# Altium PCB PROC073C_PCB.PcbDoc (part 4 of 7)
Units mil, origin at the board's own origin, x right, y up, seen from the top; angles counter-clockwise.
Board outline 2165.35 x 2695.12 mil, 8 copper layers (Top Layer, L2_GND, L3_SIGNAL 1, L4_SIGNAL 2, L5_SIGNAL 3, L6_SIGNAL 4, L7_GND, Bottom Layer), stack 55.9 mil thick; 393 components, 319 nets, 1311 pads, 1643 vias.
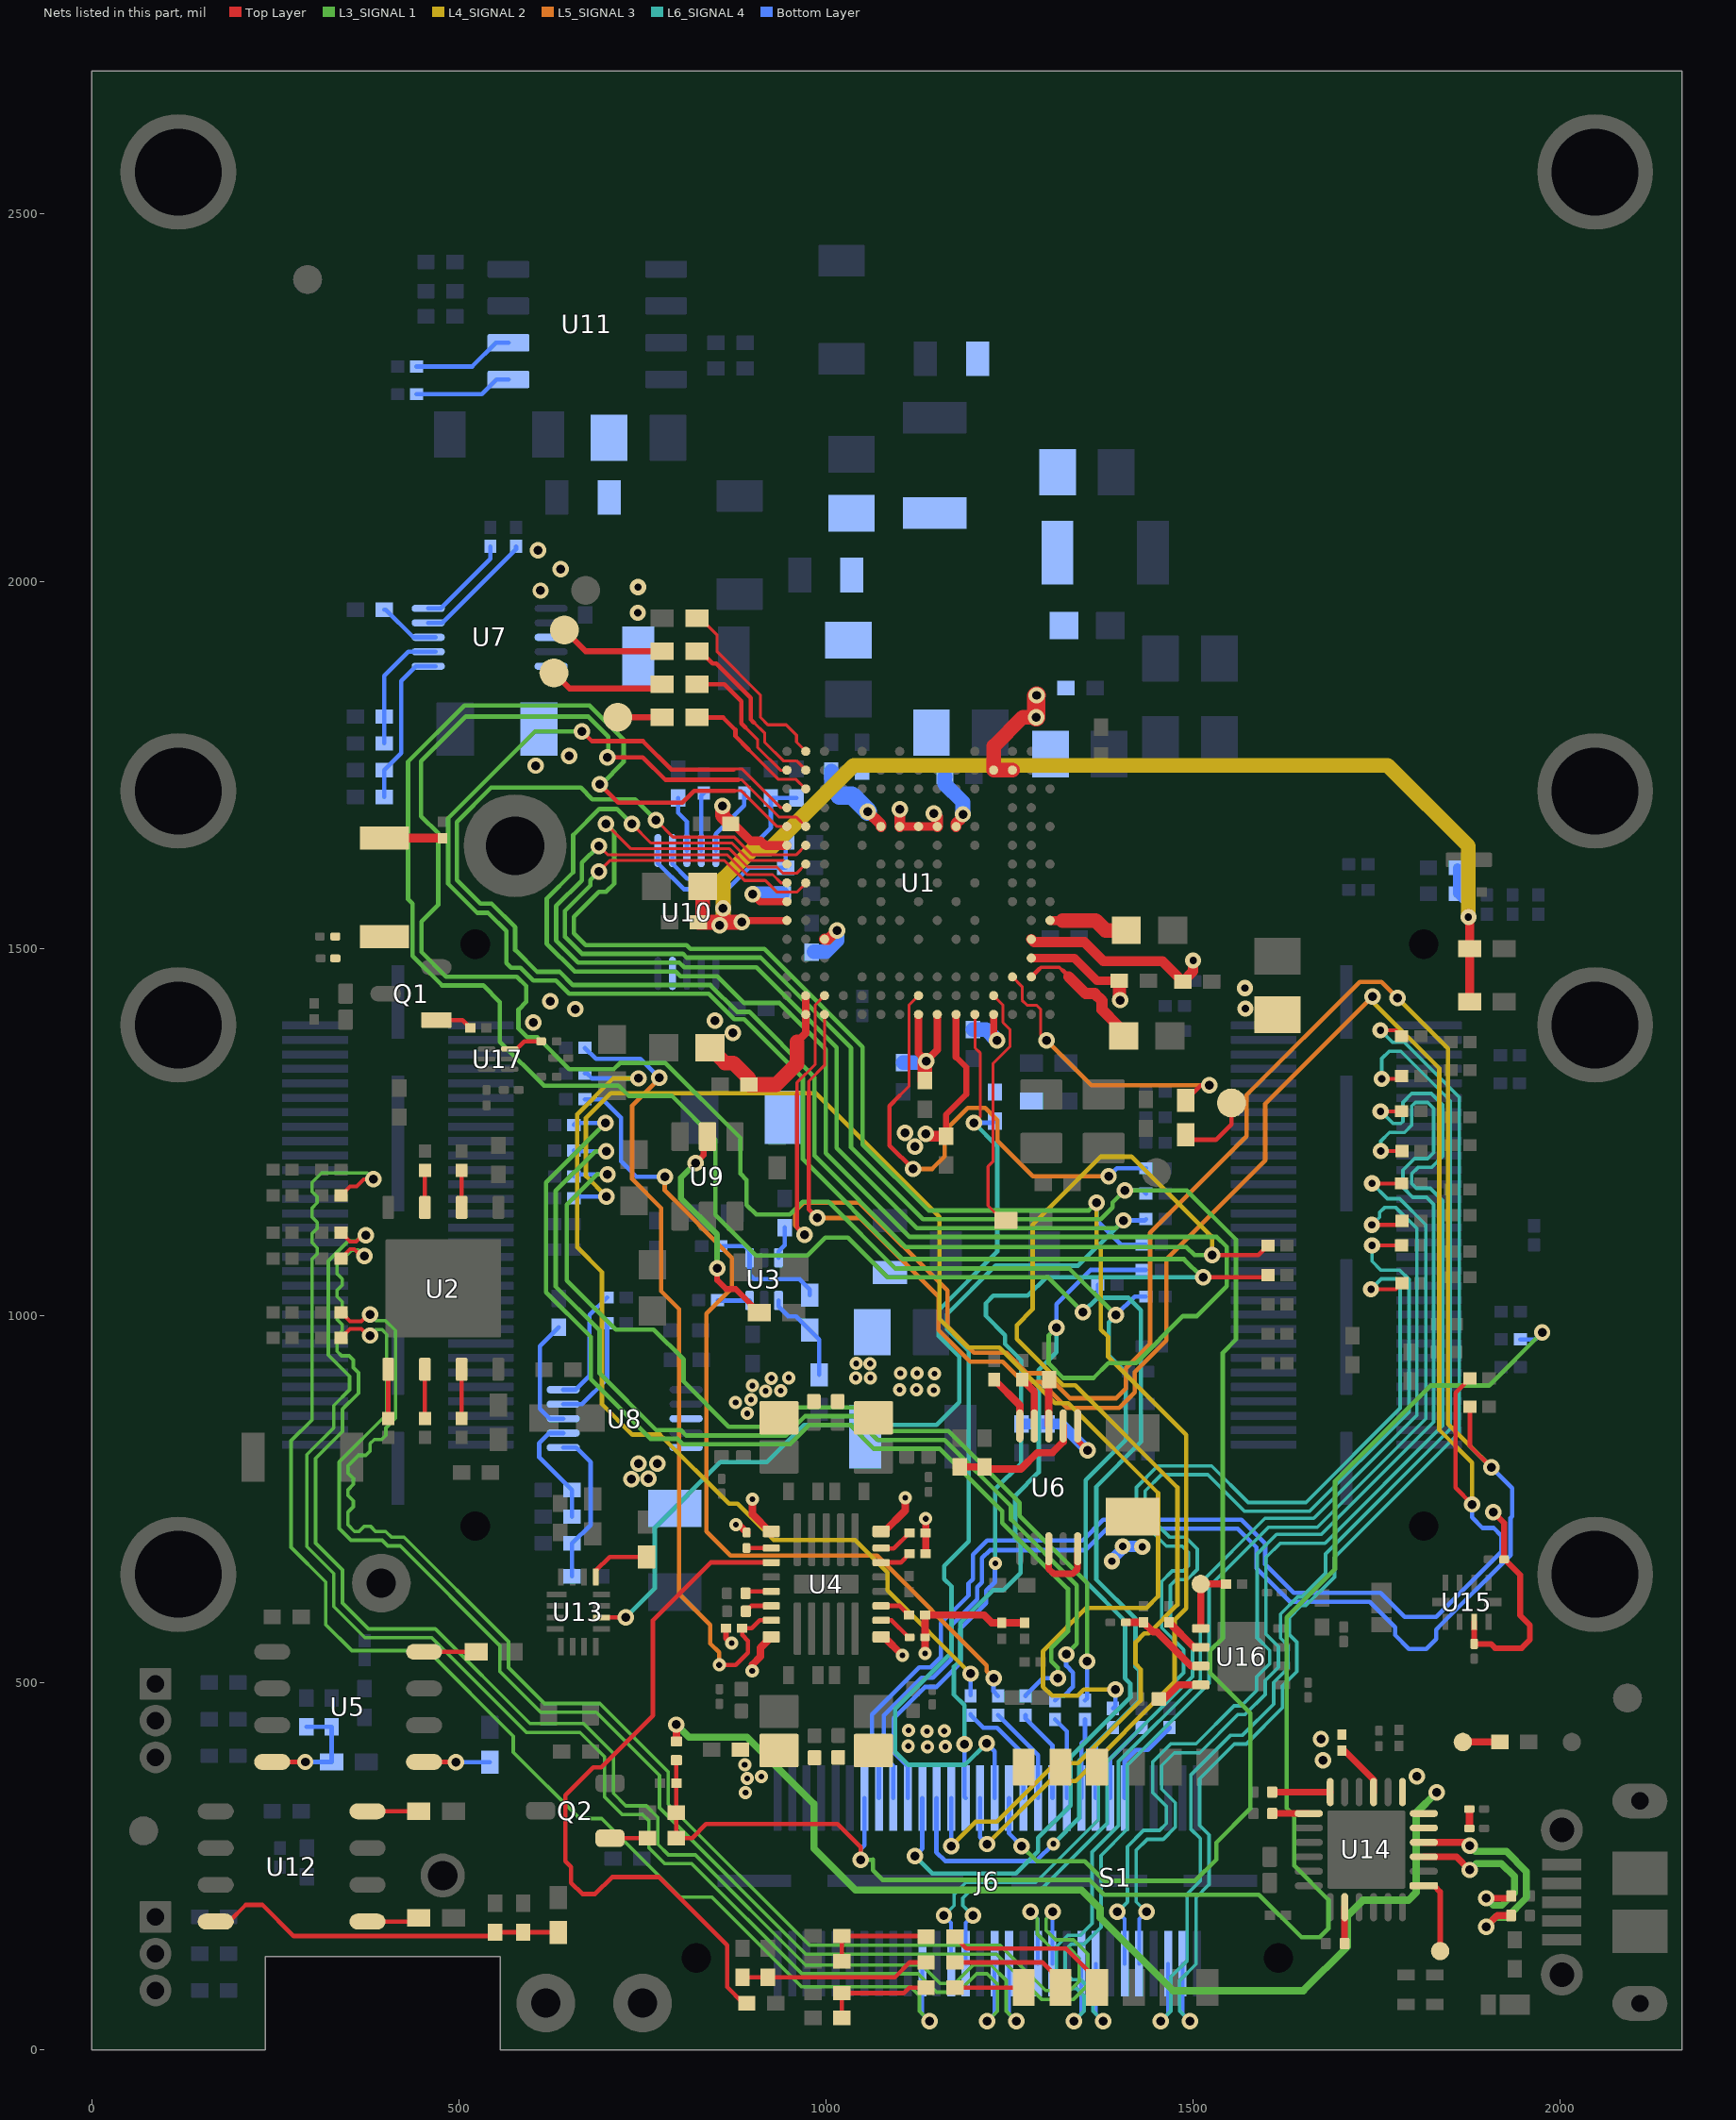
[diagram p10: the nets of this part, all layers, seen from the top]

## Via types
v1: diameter 13.77/15.74 (per signal layer), hole 5.9, Top Layer to L2_GND, tented both sides, 894 vias
v2: diameter 22.4, hole 12.2, Top Layer to Bottom Layer, tented both sides, 510 vias
v3: diameter 18, hole 8, Top Layer to Bottom Layer, tented both sides, 74 vias
v4: diameter 13.78/15.75 (per signal layer), hole 5.9, Top Layer to L2_GND, tented both sides, 72 vias
v5: diameter 22, hole 10, Top Layer to Bottom Layer, tented both sides, 61 vias
v6: diameter 19.68, hole 7.87, Top Layer to Bottom Layer, 16 vias
v7: diameter 13.77/15.74 (per signal layer), hole 5.9, Top Layer to L2_GND, tented top, 14 vias
v8: diameter 20, hole 10, Top Layer to Bottom Layer, tented both sides, 1 vias
v9: diameter 13.78/15.75 (per signal layer), hole 5.9, Top Layer to L2_GND, tented top, 1 vias

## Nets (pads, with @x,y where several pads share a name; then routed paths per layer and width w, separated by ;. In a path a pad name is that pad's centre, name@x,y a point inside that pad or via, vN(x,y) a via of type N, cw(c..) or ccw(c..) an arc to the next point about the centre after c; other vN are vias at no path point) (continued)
NetJ6_22: J6.22 R218.1 | length 1949.4
  Top Layer w5.2: R218.1@339.59,1163.84 351.99,1176.24 360.88,1176.24 370.5,1185.86 v2(383.47,1185.86)
  L3_SIGNAL 1 w4.8: v2(383.47,1185.86) 374.98,1194.35 313.13,1194.35 300.19,1181.41 300.19,1169.03 307.35,1161.87 307.35,1153.8 300.19,1146.63 300.19,1134.25 307.35,1127.09 307.35,1119.02 300.19,1111.85 300.19,1099.47 307.35,1092.31 307.35,1084.24 300.19,1077.07 300.19,858.15 271.76,829.72 271.76,684.49 318.91,637.34 318.91,579.48 354.52,543.87 457.77,543.87 574.27,427.37 574.27,405.68 664.61,315.35 694.6,315.35 801.52,208.43 844.66,208.43 966.67,86.42 1115.14,86.42 1127.31,74.24 1127.31,53.17 v2(1141.05,39.43)
  Bottom Layer w5.2: J6.22@1131.16,117.69 1131.16,49.32 v2(1141.05,39.43)
NetJ6_26: J6.26 R219.1 | length 1630.9
  Top Layer w5.2: v5(1742.18,1036.2) 1775.92,1036.2 R219.1@1784.28,1044.56
  L6_SIGNAL 4 w4.8: v2(1160.63,183.2) 1174.37,196.94 1174.37,212.1 1190.55,228.27 1285.45,228.27 1370.95,313.77 1370.95,397.69 1487.02,513.76 1487.02,545.11 1457.02,575.11 1457.02,637.99 1471.68,652.65 1486.89,652.65 1493.67,659.44 1493.67,677.53 1484.88,686.32 1463.52,686.32 1422.63,727.21 1422.63,766.42 1451.72,795.51 1525.13,795.51 1574.8,745.84 1653.63,745.84 1781.88,874.08 1781.88,1044.62 1776.33,1050.16 1756.14,1050.16 v5(1742.18,1036.2)
  Bottom Layer w5.2: v2(1160.63,183.2) 1170.53,173.3 J6.26@1170.53,117.69
NetJ6_28: J6.28 R220.1 | length 1664.8
  Top Layer w5.2: v5(1743.62,1095.72) R220.1@1783.85,1095.72
  L6_SIGNAL 4 w4.8: v2(1200.11,183.2) 1186.37,196.94 1186.37,207.13 1195.52,216.27 1290.42,216.27 1382.95,308.8 1382.95,392.72 1499.02,508.79 1499.02,550.08 1469.02,580.08 1469.02,633.02 1476.66,640.65 1491.86,640.65 1505.67,654.47 1505.67,682.5 1489.85,698.32 1468.49,698.32 1434.63,732.18 1434.63,761.45 1456.69,783.51 1520.16,783.51 1569.83,733.84 1658.61,733.84 1793.88,869.11 1793.88,1049.59 1781.3,1062.16 1755.57,1062.16 1743.62,1074.11 v5(1743.62,1095.72)
  Bottom Layer w5.2: J6.28@1190.21,117.69 1190.21,173.3 v2(1200.11,183.2)
NetJ6_32: J6.32 R221.1 | length 1959.3
  Top Layer w5.2: R221.1@339.59,1113.02 351.99,1100.62 360.08,1100.62 369.08,1109.62 v2(373.31,1109.62)
  L3_SIGNAL 1 w4.8: v2(373.31,1109.62) 368.47,1109.62 360.27,1101.42 349.22,1101.42 322.31,1074.51 322.31,946.53 351.38,917.46 351.38,899.33 329.71,877.67 329.71,847.36 293.13,810.78 293.13,685.59 329.71,649.01 329.71,604.05 372.12,561.65 463.06,561.65 592.02,432.69 665.03,432.69 698.65,399.07 698.65,344.61 722.44,320.82 750.22,320.82 759.03,312.01 759.03,275.31 780.47,253.86 817.18,253.86 967.15,103.89 1125.58,103.89 1150.66,78.81 1180.28,78.81 1205.36,103.89 1219.51,103.89 1233.42,89.98 1233.42,53.17 v2(1219.69,39.43)
  Bottom Layer w5.2: v2(1219.69,39.43) 1229.58,49.32 J6.32@1229.58,117.69
NetJ6_34: J6.34 R222.1 | length 1959.7
  Top Layer w5.2: R222.1@339.59,1078.02 351.99,1090.42 357.63,1090.42 366.83,1081.22 v2(371.54,1081.22)
  L3_SIGNAL 1 w4.8: v2(371.54,1081.22) 363.34,1089.42 354.19,1089.42 334.31,1069.54 334.31,1057.16 341.47,1049.99 341.47,1041.92 334.31,1034.76 334.31,1026.05 341.47,1018.89 341.47,1010.81 334.31,1003.65 334.31,994.94 341.47,987.78 341.47,979.71 334.31,972.55 334.31,951.5 340.47,945.34 350.59,945.34 356.3,939.63 356.3,929.5 363.38,922.43 363.38,894.36 341.71,872.7 341.71,842.39 305.13,805.81 305.13,690.56 341.71,653.98 341.71,609.02 377.09,573.65 468.03,573.65 596.99,444.69 670,444.69 710.65,404.04 710.65,349.58 727.41,332.82 755.19,332.82 771.03,316.98 771.03,280.28 785.44,265.86 822.15,265.86 972.12,115.89 1130.55,115.89 1155.63,90.81 1175.31,90.81 1200.39,115.89 1224.48,115.89 1245.42,94.95 1245.42,53.17 v2(1259.16,39.43)
  Bottom Layer w5.2: J6.34@1249.27,117.69 1249.27,49.32 v2(1259.16,39.43)
NetJ6_35: J6.35 R148.2 | length 155.1
  Bottom Layer w6: R148.2@1196.94,457.46 R148.2@1196.94,456.22 1214,439.16 1232.89,439.16 1268.95,403.11 J6.35@1268.95,343.28
NetJ6_37: J6.37 R149.2 | length 135.4
  Bottom Layer w6: R149.2@1234.31,456.22 1288.64,401.89 J6.37@1288.64,343.28
NetJ6_38: J6.38 R223.1 | length 1933.7
  Top Layer w5.2: R223.1@339.59,1004.77 351.99,992.37 367.5,992.37 376.59,1001.46 v2(379.02,1001.46)
  L3_SIGNAL 1 w4.8: v2(379.02,1001.46) 387.22,993.26 400.27,993.26 413.84,979.7 413.84,860.42 400.77,847.35 400.77,837.22 395.06,831.51 384.93,831.51 379.22,825.8 379.22,815.67 373.52,809.97 363.39,809.97 349.2,795.78 349.2,785.54 356.37,778.37 356.37,770.3 349.2,763.14 349.2,755.07 356.37,747.91 356.37,739.83 349.2,732.67 349.2,715.18 358.13,706.25 364.31,706.25 371.47,713.41 379.54,713.41 386.7,706.25 400.51,706.25 408.29,698.47 425.38,698.47 567.72,556.13 567.72,520.98 616.52,472.18 692.06,472.18 785.26,378.98 785.26,335 977.48,142.78 1237.24,142.78 1298.95,81.07 1332.07,81.07 1344.69,93.69 1344.69,125.63 1332.05,138.28 1307.45,138.28 1287.86,157.87 1287.86,178.77 1278.74,187.88 v2(1278.74,188.2)
  Bottom Layer w5.2: v2(1278.74,188.2) 1288.64,178.3 J6.38@1288.64,117.69
NetJ6_39: J6.39 R163.2 | length 128.1
  Bottom Layer w6: R163.2@1271.67,456.22 1271.67,452.07 1308.32,415.42 J6.39@1308.32,343.28
NetJ6_40: J6.40 R224.1 | length 1920.9
  Top Layer w5.2: R224.1@339.59,969.77 351.99,982.17 367.48,982.17 376.59,973.06 v2(379.02,973.06)
  L3_SIGNAL 1 w4.8: v2(379.02,973.06) 387.22,981.26 395.3,981.26 401.84,974.73 401.84,865.39 337.2,800.76 337.2,710.21 353.16,694.25 395.54,694.25 403.32,686.47 420.41,686.47 555.72,551.16 555.72,516.01 611.55,460.18 687.09,460.18 773.26,374.01 773.26,330.03 972.51,130.78 1232.27,130.78 1294.2,68.85 1336.82,68.85 1356.69,88.72 1356.69,130.6 1337.02,150.28 1312.42,150.28 1299.86,162.84 1299.86,178.77 1308.97,187.88 v2(1308.97,188.2)
  Bottom Layer w5.2: J6.40@1308.32,117.69 1308.32,188.15 v2@1308.97,188.8
NetJ6_41: J6.41 R164.2 | length 113.6
  Bottom Layer w6: R164.2@1311.95,450.23 1328.01,434.17 J6.41@1328.01,343.28
NetJ6_43: J6.43 R166.2 | length 109
  Bottom Layer w6: J6.43@1347.69,343.28 1347.69,417.53 1352.68,422.52 R166.2@1352.68,450.23
NetJ6_44: J6.44 R225.1 | length 1572
  Top Layer w5.2: v5(1743.35,1123.72) 1778.97,1123.72 R225.1@1784.28,1129.03
  L6_SIGNAL 4 w4.8: v2(1337.8,39.43) 1351.53,53.17 1351.53,73.72 1341.14,84.11 1329.62,84.11 1313.76,99.97 1313.76,140.88 1329.26,156.38 1346.44,156.38 1362.42,172.37 1362.42,269.88 1398.31,305.77 1398.31,392.94 1509.65,504.28 1509.65,635.99 1597.69,724.04 1664.08,724.04 1804.68,864.64 1804.68,1118.81 1776.17,1147.32 1760.45,1147.32 1753.74,1140.61 1753.74,1134.11 v5(1743.35,1123.72)
  Bottom Layer w5.2: v2(1337.8,39.43) 1347.69,49.32 J6.44@1347.69,117.69
NetJ6_45: J6.45 R167.2 | length 105.8
  Bottom Layer w6: J6.45@1367.38,343.28 1367.38,415.98 R167.2@1390.77,439.38
NetJ6_46: J6.46 R226.1 | length 1583.7
  Top Layer w5.2: v5(1743.62,1180.18) R226.1@1783.85,1180.18
  L6_SIGNAL 4 w4.8: v2(1377.27,39.43) 1363.53,53.17 1363.53,78.69 1346.11,96.11 1334.59,96.11 1325.76,104.94 1325.76,135.91 1334.23,144.38 1351.41,144.38 1374.42,167.4 1374.42,264.91 1410.31,300.8 1410.31,387.97 1521.65,499.31 1521.65,631.02 1602.67,712.04 1669.05,712.04 1816.68,859.67 1816.68,1123.78 1781.14,1159.32 1764.49,1159.32 v5(1743.62,1180.18)
  Bottom Layer w5.2: J6.46@1367.38,117.69 1367.38,49.32 v2(1377.27,39.43)
NetJ6_47: J6.47 R168.2 | length 113.9
  Bottom Layer w6: J6.47@1387.06,343.28 1387.06,396.52 R168.2@1429.92,439.38
NetJ6_49: J6.49 R170.2 | length 130.8
  Bottom Layer w6: J6.49@1406.75,343.28 1406.75,393.1 1422.61,408.97 1438.62,408.97 1467.83,438.18 R170.2@1467.83,439.38
NetJ6_50: J6.50 R227.1 | length 1662.4
  Top Layer w5.2: v5(1755.37,1224.38) R227.1@1784.28,1224.38
  L6_SIGNAL 4 w4.8: v2(1396.85,188.2) 1410.46,201.81 1410.46,277.23 1432.38,299.14 1454.19,299.14 1463.62,308.57 1463.62,331.94 1445.01,350.56 1445.01,392.52 1469.51,417.03 1504,417.03 1555.82,468.84 1565.64,468.84 1586.1,489.31 1586.1,508.08 1604.1,526.08 1604.1,544.43 1587.16,561.36 1587.16,675.75 1613.65,702.24 1674.52,702.24 1827.48,855.2 1827.48,1151.71 1817.81,1161.37 1798.93,1161.37 1785.54,1174.76 1785.54,1198.19 1801.27,1213.92 1819.41,1213.92 1827.48,1222 1827.48,1282.33 1819.26,1290.54 1802.62,1290.54 1797.58,1285.5 1797.58,1259.47 1787.83,1249.72 1767.2,1249.72 1755.37,1237.89 v5(1755.37,1224.38)
  Bottom Layer w5.2: v2(1396.85,188.2) 1406.75,178.3 J6.50@1406.75,117.69
NetJ6_52: J6.52 R228.1 | length 1671
  Top Layer w5.2: v5(1755.14,1278.29) 1783.63,1278.29 R228.1@1783.85,1278.52
  L6_SIGNAL 4 w4.8: v2(1436.33,188.2) 1422.46,202.07 1422.46,272.26 1437.35,287.14 1459.16,287.14 1475.62,303.6 1475.62,336.91 1457.01,355.53 1457.01,387.55 1474.48,405.03 1508.97,405.03 1560.79,456.84 1570.61,456.84 1598.1,484.33 1598.1,503.11 1616.1,521.11 1616.1,549.4 1599.16,566.33 1599.16,670.78 1618.62,690.24 1679.49,690.24 1839.48,850.23 1839.48,1156.68 1822.79,1173.37 1803.9,1173.37 1797.54,1179.73 1797.54,1193.22 1806.24,1201.92 1824.38,1201.92 1839.48,1217.03 1839.48,1287.3 1824.23,1302.54 1797.65,1302.54 1785.58,1290.47 1785.58,1264.44 1782.86,1261.72 1772.17,1261.72 1755.6,1278.29 v5(1755.14,1278.29)
  Bottom Layer w5.2: J6.52@1426.43,117.69 1426.43,178.3 v2(1436.33,188.2)
NetJ6_56: J6.56 R229.1 | length 1712.9
  Top Layer w5.2: v5(1756.84,1322.52) 1780.15,1322.52 R229.1@1783.85,1326.22
  L6_SIGNAL 4 w4.8: v2(1455.91,39.43) 1469.64,53.17 1469.64,99.86 1491.92,122.14 1491.92,212.81 1509.62,230.51 1509.62,288.19 1496.76,301.05 1496.76,374.52 1551.09,428.86 1567.34,428.86 1609.55,471.07 1609.55,500.7 1629.22,520.37 1629.22,550.58 1618.87,560.93 1618.87,593.88 1642.25,617.26 1648.32,617.26 1680.35,649.3 1680.35,675.83 1850.28,845.75 1850.28,1292.56 1782.66,1360.18 1766.99,1360.18 1756.84,1350.03 v5(1756.84,1322.52)
  Bottom Layer w5.2: v2(1455.91,39.43) 1465.8,49.32 J6.56@1465.8,117.69
NetJ6_58: J6.58 R230.1 | length 1713.2
  Top Layer w5.2: v5(1755,1388.58) 1775.98,1388.58 R230.1@1783.85,1380.71
  L6_SIGNAL 4 w4.8: v2(1495.38,39.43) 1481.64,53.17 1481.64,94.89 1503.92,117.17 1503.92,207.84 1520.68,224.59 1521.62,225.54 1521.62,293.16 1508.76,306.02 1508.76,369.55 1556.06,416.86 1572.31,416.86 1621.55,466.1 1621.55,495.73 1641.22,515.4 1641.22,555.55 1630.87,565.9 1630.87,588.91 1647.22,605.26 1653.29,605.26 1692.35,644.33 1692.35,670.85 1862.28,840.78 1862.28,1297.53 1787.63,1372.18 1771.39,1372.18 v5(1755,1388.58)
  Bottom Layer w5.2: J6.58@1485.49,117.69 1485.49,49.32 v2(1495.38,39.43)
NetQ1_1: Q1.1 R171.2 | length 50.6
  Top Layer w6: Q1.1@469.47,1402.58 505.1,1402.58 R171.2@515.68,1391.99
NetQ2_1: Q2.1 R179.2 | length 51.6
  Top Layer w6: Q2.1@705.91,288.6 R179.2@757.47,288.6
NetR2_1: R2.1 R101.2 U6.2 | length 179.2
  Top Layer w10: R101.2@1182.13,794.19 R2.1@1215.81,794.22 1218.77,791.26 1265.4,791.26 1287.55,813.41 1308.25,813.41 1323.04,828.2 U6.2@1323.04,849.93
NetR3_1: R3.1 R70.2 R71.1 U5.8 | length 163.1
  Top Layer w6: U5.8@245.94,392.41 v2(290.94,392.41)
  Bottom Layer w6: v2(290.94,392.41) R3.1@326.89,392.41 R70.2@326.89,440.22 R71.1@292.59,440.22
NetR14_1: R14.1 R103.2 U6.1 | length 143.9
  Top Layer w8: U6.1@1342.73,849.93 1342.73,830.32 v2(1356.41,816.64)
  Bottom Layer w15: R103.2@1266.47,852.83 1320.22,852.83 v2(1356.41,816.64)
NetR25_1: R25.1 U6.5 | length 77.6
  Top Layer w10: R25.1@1229.01,913.08 1263.99,878.1 U6.5@1263.99,849.93
NetR29_1: R29.1 U6.4 | length 70
  Top Layer w10: R29.1@1267.18,913.08 1283.67,896.58 U6.4@1283.67,849.93
NetR45_1: R45.1 U2.5 | length 66.8
  Top Layer w6: R45.1@403.88,860.18 U2.5@403.88,926.95
NetR46_2: R46.2 U2.2 | length 50.7
  Top Layer w6: U2.2@503.88,1147.43 R46.2@503.88,1198.11
NetR47_2: R47.2 U2.3 | length 50.7
  Top Layer w6: U2.3@453.88,1147.43 R47.2@453.88,1198.11
NetR48_1: R48.1 U2.6 | length 66.8
  Top Layer w6: R48.1@453.88,860.18 U2.6@453.88,926.95
NetR51_1: R51.1 U2.7 | length 66.8
  Top Layer w6: R51.1@503.88,860.18 U2.7@503.88,926.95
NetR54_1: R54.1 U3.3 | length 44.6
  Bottom Layer w6: U3.3@935.43,1078.9 935.43,1087.51 943.74,1095.83 R54.1@943.74,1120.09
NetR55_2: R55.2 U3.6 | length 43.8
  Bottom Layer w6: R55.2@852.47,1021.13 852.97,1020.64 U3.6@896.06,1020.64
NetR56_2: R56.2 R151.1 U3.1 | length 172.4
  Bottom Layer w6: R56.2@856.74,1094.77 889.16,1094.77 896.06,1087.87 896.06,1055.71 902,1049.77 964,1049.77 977.93,1035.84 R151.1@977.93,1027.84
NetR57_1: R57.1 R151.2 U3.4 | length 130.1
  Bottom Layer w6: U3.4@935.43,1020.64 935.43,1012.53 948.74,999.22 959.31,999.22 R151.2@977.93,980.6 990.93,967.6 R57.1@990.93,919.72
NetR72_2: R72.2 U1.P1 | length 260.2
  Top Layer w4.02: R72.2@824.21,1949.77 828.74,1949.77 851.87,1926.64 851.87,1904.07 910.74,1845.2 910.74,1814.77 920.91,1804.6 945.93,1804.6 959.85,1790.67 959.85,1781.1 U1.P1@972.43,1768.52 U1.P1@972.64,1768.31
NetR73_2: R73.2 U1.P2 | length 239.8
  Top Layer w4: 901.74,1807.95 916.74,1792.95 916.74,1780.57 941.73,1755.58 959.78,1755.58 U1.P2@972.64,1742.72
  Top Layer w6: R73.2@824.21,1904.77 828.74,1904.77 845.37,1888.14 850.59,1888.14 897.74,1840.99 897.74,1811.95 901.74,1807.95
NetR74_2: R74.2 U1.P3 | length 193.7
  Top Layer w4: 895.24,1770.48 935.43,1730.29 959.48,1730.29 U1.P3@972.43,1717.34
  Top Layer w6: R74.2@824.21,1814.77 824.41,1814.57 859.94,1814.57 876.74,1797.77 876.74,1788.97 895.24,1770.48
NetR75_2: R75.2 U1.R2 | length 195
  Top Layer w4.02: 890.74,1800.74 906.73,1784.75 906.73,1774.11 938.12,1742.72 U1.R2@947.05,1742.72
  Top Layer w6: R75.2@824.21,1859.77 861.57,1859.77 884.74,1836.6 884.74,1806.74 890.74,1800.74
NetR76_2: R76.2 U1.C13 | length 400.4
  Top Layer w4: U1.C13@1254.13,1461.22 1267.08,1448.28 1267.08,1429.63 1274.08,1422.63 1287.08,1422.63 1292.08,1417.63 1292.08,1383.28 v2(1300.59,1374.77)
  Top Layer w6: R76.2@1490,1293.39 1510.38,1313.77 v2(1522,1313.77)
  L5_SIGNAL 3 w6: v2(1300.59,1374.77) 1361.59,1313.77 v2(1522,1313.77)
NetR77_2: R77.2 U1.D14 | length 340
  Top Layer w4: U1.D14@1228.54,1435.63 1241,1423.18 1241,1399.36 1250.59,1389.77 1250.59,1366.31 1227.29,1343.01 1227.29,1209.82 1220.74,1203.27 1220.74,1149.77 1240.74,1129.77 R77.2@1245.12,1129.77
NetR78_2: R78.2 U5.1 | length 91.4
  Top Layer w6: U5.1@452.64,392.41 v2@497.63,392.41
  Bottom Layer w6: v2(495.99,392.09) R78.2@542.39,392.09
NetR80_2: R80.2 U5.4 | length 71.2
  Top Layer w6: U5.4@452.64,542.41 R80.2@523.88,542.41
NetR83_2: R83.2 R84.1 R216.1 U12.8 | length 495.6
  Top Layer w6: U12.8@169.09,175.13 187.33,175.13 209.99,197.79 232.95,197.79 275.44,155.3 544.39,155.3 R83.2@549.57,160.48 R84.1@587.71,160.48 R216.1@635.54,160.48
NetR85_2: R85.2 U12.1 | length 71.7
  Top Layer w6: U12.1@375.78,175.13 440.44,175.13 R85.2@445.44,180.13
NetR87_2: R87.2 U12.4 | length 69.7
  Top Layer w6: U12.4@375.78,325.13 R87.2@445.44,325.13
NetR89_2: R89.2 U13.13 | length 85.3
  Top Layer w6: U13.13@686.41,644.19 686.41,652.64 705.38,671.61 R89.2@755.42,671.61
NetR91_1: R91.1 U14.3 | length 248.9
  Top Layer w9.42: U14.3@1814.14,263.2 1858.43,263.2 v2(1876.29,245.34) ; v2(1898.86,206.79) 1929.73,206.79 R91.1@1932.91,209.97
  L3_SIGNAL 1 w9.42: v2(1876.29,245.34) 1885.13,254.18 1919.66,254.18 1937.37,236.47 1937.37,214.13 1920.32,197.08 1908.57,197.08 v2(1898.86,206.79)
NetR92_1: R92.1 U14.4 | length 303.5
  Top Layer w9.42: U14.4@1814.14,282.88 1871.86,282.88 v2(1876.29,278.45) ; v2(1898.86,168.11) 1914.06,183.31 R92.1@1932.91,183.31
  L3_SIGNAL 1 w9.42: v2(1876.29,278.45) 1884.13,270.61 1926.46,270.61 1953.79,243.27 1953.79,207.33 1927.12,180.66 1911.41,180.66 v2(1898.86,168.11)
NetR93_2: R93.2 U14.9 | length 76.2
  Top Layer w9: R93.2@1702.37,407.66 1705.75,407.66 1745.65,367.76 U14.9@1745.65,351.37
NetR94_2: R94.2 U6.3 | length 63.4
  Top Layer w10: U6.3@1303.36,849.93 1303.36,912.57 R94.2@1303.87,913.08
NetR96_1: R96.1 U14.20 | length 49.5
  Top Layer w9: R96.1@1706.28,145.26 U14.20@1706.28,194.71
NetR97_1: R97.1 U14.12 | length 79
  Top Layer w9: R97.1@1607.62,351.37 U14.12@1686.6,351.37
NetR98_2: R98.2 U14.13 | length 49.9
  Top Layer w9: R98.2@1607.62,322.25 U14.13@1657.48,322.25
NetR102_2: R102.2 R120.2 U16.3 | length 126.7
  Top Layer w10: R102.2@1408.25,582.46 R120.2@1432.23,582.48 ; R120.2@1432.23,582.48 1445.38,569.33 1450.87,569.33 1497.11,523.08 U16.3@1510.32,523.08
NetR104_1: R104.1 R113.2 U7.2 | length 175.5
  Bottom Layer w6: R104.1@398.53,1779.32 R113.2@398.53,1815.75 398.53,1871.44 431.15,1904.06 U7.2@458.41,1904.06 U7.2@468.41,1904.06
NetR105_1: R105.1 R114.2 U7.1 | length 222.5
  Bottom Layer w6: R114.2@398.53,1706.46 R105.1@398.53,1742.89 421.59,1765.95 421.59,1864.34 441.62,1884.37 U7.1@458.41,1884.37 U7.1@468.41,1884.37
NetR106_1: R106.1 R116.2 U8.2 | length 157.1
  Bottom Layer w6: U8.2@642.2,840.21 623.2,840.21 609.47,826.48 609.47,807.42 R116.2@654.32,762.57 R106.1@654.32,726.36
NetR107_1: R107.1 R117.2 U8.1 | length 211.5
  Bottom Layer w6: U8.1@642.2,820.53 659.67,820.53 679.64,800.56 679.64,715.46 R117.2@654.32,690.14 R107.1@654.32,645.31
NetR108_1: R108.1 U7.5 | length 129.5
  Bottom Layer w6: U7.5@458.41,1963.11 475.48,1963.11 542.98,2030.62 R108.1@542.98,2047.59
NetR109_1: R109.1 U8.5 | length 160.4
  Bottom Layer w6: U8.5@642.2,899.27 659.4,899.27 678.11,917.98 678.11,1000.87 R109.1@702.01,1024.77
NetR110_1: R110.1 U7.4 | length 165
  Bottom Layer w6: U7.4@458.41,1943.43 477.67,1943.43 577.98,2043.74 R110.1@577.98,2047.59
NetR111_1: R111.1 U8.4 | length 149.9
  Bottom Layer w6: U8.4@642.2,879.59 667.74,879.59 702.01,913.85 R111.1@702.01,989.77
NetR112_2: R112.2 U7.3 | length 85.5
  Bottom Layer w6: R112.2@398.53,1961.46 400.43,1961.46 438.16,1923.74 U7.3@458.41,1923.74 U7.3@468.41,1923.74
NetR115_2: R115.2 U8.3 | length 159.1
  Bottom Layer w6: R115.2@636.16,984.35 610.41,958.6 610.41,873.29 623.8,859.9 U8.3@642.2,859.9
NetR118_2: R118.2 TP8.1 U16.1 | length 94.9
  Top Layer w10: U16.1@1510.32,574.26 TP8.1@1510.32,634.76 R118.2@1544.77,634.76
NetR119_1: R119.1 U16.2 | length 57.3
  Top Layer w10: R119.1@1467.08,582.48 1500.89,548.67 U16.2@1510.32,548.67
NetR121_2: R121.2 U16.4 | length 65
  Top Layer w10: R121.2@1453.31,478.28 1460.9,478.28 1480.1,497.49 U16.4@1510.32,497.49
NetR138_2: R138.2 U17.3 | length 47.2
  Top Layer w6: U17.3@569.32,1363.26 578.93,1363.26 589.3,1373.63 R138.2@612.21,1373.63
NetR139_1: R139.1 R146.2 U10.2 | length 264.5
  Bottom Layer w6: U10.2@790.91,1633.43 790.9,1615.45 811.08,1595.27 855.5,1595.27 925,1664.77 R146.2@925,1705.08 R139.1@960,1705.09
NetR142_1: R142.1 R147.2 U10.1 | length 253.1
  Bottom Layer w6: U10.1@771.22,1633.43 771.22,1616.06 806.51,1580.77 866,1580.77 895,1609.77 R147.2@945.31,1609.77 R142.1@945.32,1644.77
NetR143_1: R143.1 U10.5 | length 94.4
  Bottom Layer w6: U10.5@849.96,1633.43 849.96,1655.99 888.74,1694.77 R143.1@888.74,1711.78
NetR144_1: R144.1 U10.4 | length 79.8
  Bottom Layer w6: U10.4@830.28,1633.43 830.27,1708.31 R144.1@833.74,1711.78
NetR145_2: R145.2 U10.3 | length 76.6
  Bottom Layer w6: R145.2@798.74,1705.09 798.74,1684.77 810.59,1672.92 U10.3@810.59,1633.43
NetR159_1: R159.1 U11.6 | length 138.5
  Bottom Layer w6: R159.1@442.58,2292.44 518.2,2292.44 550.53,2324.77 U11.6@567.72,2324.77
NetR160_1: R160.1 U11.5 | length 133.4
  Bottom Layer w6: R160.1@442.58,2254.9 531.38,2254.9 551.25,2274.77 U11.5@567.72,2274.77
NetR196_2: R196.2 U9.5 | length 306.3
  Top Layer w8: v2(822.43,1207.86) 833.46,1218.88 833.46,1238.62 U9.5@838.74,1243.9 ; v2(851.75,1064.74) 851.75,1048.52 864.05,1036.22 877.13,1036.22 R196.2@908.98,1004.37
  L3_SIGNAL 1 w8: v2(822.43,1207.86) 802.54,1187.97 802.54,1159.73 851.75,1110.52 v2(851.75,1064.74)
NetR203_2: R203.2 R204.1 R205.2 | length 151.4
  Top Layer w6: R205.2@1021.73,43.89 R203.2@1021.73,77.62 1105.92,77.62 1113.46,85.15 R204.1@1136.29,85.15
NetR204_2: R204.2 S1.1 | length 93.5
  Top Layer w6: R204.2@1175.66,85.15 S1.1@1269.21,85.15
NetR206_2: R206.2 R207.1 R208.2 | length 258.4
  Top Layer w6: R208.2@886.26,99.3 R206.2@920.56,99.3 1093.84,99.3 1114.01,119.47 R207.1@1136.29,119.47
NetR207_2: R207.2 S1.2 | length 163.3
  Top Layer w6: R207.2@1175.66,119.47 1294.32,119.47 1319.21,94.58 S1.2@1319.21,85.15
NetR209_2: R209.2 R210.1 R211.2 | length 148.5
  Top Layer w6: R211.2@1021.73,120.94 R209.2@1021.73,154.42 ; R209.2@1021.73,155.42 1135.29,155.42 R210.1@1136.29,154.42
NetR210_2: R210.2 S1.3 | length 228.4
  Top Layer w6: R210.2@1175.66,153.78 1191.03,138.41 1326.9,138.41 1369.21,96.1 S1.3@1369.21,85.15
NetR213_1: R213.1 S3.2 | length 79.3
  Top Layer w12: S3.2@398.63,1650.24 R213.1@477.94,1650.24
NetR214_1: R214.1 R215.2 S3.1
NetTP1_1: TP1.1 U14.1 | length 106.3
  Top Layer w8: U14.1@1814.14,223.83 1828.09,223.83 1836.32,215.59 TP1.1@1836.32,134.9
PGOOD: J6.13 R13.2 R179.1 R182.2 R198.1 R201.2 | length 2236.1
  Top Layer w6: R198.1@796.29,394.85 R182.2@796.29,323.18 R179.1@796.29,288.6 817.72,288.6 836.85,307.73 1015.97,307.73 1047.36,276.34 v2(1047.36,259.1)
  L3_SIGNAL 1 w6: v2(1047.36,259.1) 1062.93,259.1 1063.77,259.93 1063.77,245.1 1076.99,231.88 1358.51,231.88 1378.73,211.66 1589.53,211.66 1647.56,153.63 1672.49,153.63 1684.07,165.21 1684.07,204.83 1637.71,251.19 1637.71,319.2 1627.46,329.45 1627.46,589.41 1693.21,655.17 1693.21,775.09 1823.07,904.95 1903.04,904.95 v2(1975.14,977.05)
  Bottom Layer w6: v2(1047.36,259.1) 1047.36,274.13 1052.42,279.19 J6.13@1052.42,343.28 ; R13.2@1945.35,967.82 1965.91,967.82 v2(1975.14,977.05)
PMIC_1V0: C66.1 L6.1 R199.1 U4.1 U7.8 U7.10 | length 55.9
  Top Layer w10: v3(899.89,750.35) 899.89,729.75 923.31,706.33 U4.1@925.53,706.33
  other v2: 601.54,1399.37 658.78,1417.56 624.34,1428.01 604.7,1749.01 650.42,1762.42
  other v3: 892.86,866.84 877.02,881.89 898.08,885.59 917.87,897.49 938.49,897.98 899.69,904.74 925.74,914.81 949.46,915.49
PMIC_1V2: C62.1 L5.1 R193.1 U4.14 U8.8 U8.10 | length 39.1
  Top Layer w5.5: U4.14@1075.13,562.63 U4.14@1079.07,562.63
  Top Layer w10: U4.14@1079.07,562.63 v3(1103.95,537.75)
  other v2: 735.09,777.47 758.48,778.37 744.73,798.74 770.32,798.49
  other v3: 1138.38,413.11 1112.03,413.92 1162.47,413.32 1137.61,434.3 1161.07,434.5 1112.33,435.37
PMIC_1V8: C67.1 L8.1 R192.1 U4.21 U6.8 U6.10 | length 214.4
  Top Layer w9: U6.8@1303.36,682.61 1303.36,655.27 1310.07,648.56 1335.8,648.56 1342.73,655.49 U6.10@1342.73,682.61
  Top Layer w10: U4.21@1075.13,706.33 1079.59,706.33 1107.94,734.68 v3(1107.94,752)
  Bottom Layer w15: v5(1389.19,665.71) 1389.19,667.77 1404.24,682.81 v5(1404.24,686.06) v5@1430.74,686.06
  other v3: 1146.72,898.68 1100.26,899.36 1123.08,899.41 1147.84,921.1 1101.37,921.78 1124.2,921.83
  other v5: 1430.74,685.34
PMIC_3V3: C61.1 L4.1 L12.2 U4.8 | length 57.1
  Top Layer w10: v3(899.54,516.33) 899.54,524.61 910.76,535.83 910.76,547.87 U4.8@925.53,562.63
  other v3: 890.52,350.82 892.73,370.09 912.21,372.62 889.27,388.65
PMIC_CLK: R202.2 U4.3 | length 969.3
  Top Layer w6: R202.2@892.19,64.04 887.49,64.04 865.54,85.99 865.54,142.78 772.71,235.61 708.71,235.61 685.72,212.62 668.23,212.62 653.07,227.78 653.07,249.47 645.25,257.29 645.25,347.13 683.28,385.15 693.72,385.15 764.37,455.8 764.37,585.5 842.88,664.01 U4.3@925.53,664.01
PMIC_EN1: R140.1 R188.1 U4.7 | length 1108.6
  Top Layer w6: v3(854.61,524.55) 877.19,524.55 893.81,541.17 893.81,557.43 885.96,565.28 R188.1@885.96,574.5 898.93,574.5 909.7,585.27 U4.7@925.53,585.27
  L5_SIGNAL 3 w6: v2(773.04,1323.93) 773.04,1322.99 736.17,1286.12 736.17,1186.03 775.68,1146.52 775.68,1033.43 800.07,1009.04 800.07,621.61 842.54,579.14 842.54,553.66 854.61,541.59 v3(854.61,524.55)
  Bottom Layer w6: R140.1@671.74,1364.77 686.71,1349.79 747.18,1349.79 v2(773.04,1323.93)
PMIC_EN2: R189.1 U4.15 | length 48.4
  Top Layer w6: U4.15@1075.13,585.27 1089.29,585.27 1112.56,562 R189.1@1113.9,562
PMIC_EN3: R190.1 U4.2 | length 33.6
  Top Layer w6: R190.1@891.97,683.69 U4.2@925.53,683.69
PMIC_NINT: R177.1 U4.19 | length 43.6
  Top Layer w6: U4.19@1075.13,664.01 1101.78,664.01 R177.1@1113.78,676.01
PMIC_NRST: R187.1 U4.20 | length 47.8
  Top Layer w6: U4.20@1075.13,683.69 1075.82,683 1092.43,683 R187.1@1113.78,704.35
PMIC_PGOOD: R176.1 U4.16 | length 43
  Top Layer w6: U4.16@1075.13,604.95 1100.49,604.95 R176.1@1112.94,592.5
PMIC_SCL: R181.2 U4.5 | length 36
  Top Layer w6: R181.2@890.6,622 893.24,624.64 U4.5@925.53,624.64
PMIC_SDA: R180.2 U4.6 | length 37.7
  Top Layer w6: R180.2@890.94,597.5 898.39,604.95 U4.6@925.53,604.95
PMICOUT_3V3: C44.2 C45.2 C48.1 L11.1 R93.1 R100.2 R198.2 S1.10 S1.11 S1.12 TP10.1 U14.5 U14.6 U14.7 U15.8 | length 1835.2
  Top Layer w7.87: U15.8@1882.6,583.41 C48.1@1882.6,553.12 1905.58,553.12 1911.29,547.41 1947.13,547.41 1958.57,558.85 1958.57,578.57 1945.19,591.95 1945.19,647.14 1924.16,668.16 R100.2@1923.32,668.16 1923.42,668.26 1923.42,717.68 v2(1908.49,732.61)
  Top Layer w10: R198.2@796.29,420.44 v2(796.29,443.16) ; TP10.1@1867.15,419.58 L11.1@1917.5,419.58 ; C44.2@1876.11,301.92 C45.2@1876.11,328.23
  L3_SIGNAL 1 w10: v2(796.29,443.16) 813.35,426.1 892.57,426.1 983.59,335.07 983.59,274.71 1040.43,217.88 1348,217.88 1373.08,192.8 1373.08,180.58 1472.64,81.01 1649.95,81.01 1710.06,141.12 1710.06,183.09 1731.04,204.07 1792.99,204.07 1803.66,214.74 1803.66,323.07 v2(1831.39,350.8)
  other v2: 1804.41,372.66 1676.57,394.51 1673.89,423.82 611.41,1987.35 638.98,2016.51 607.69,2042.36
PMICVIO_3V3: R176.2 R177.2 R186.1 R187.2 R188.2 R189.2 R190.2 R194.2 | length 281.7
  Top Layer w8: R188.2@863.91,574.5 863.91,560.87 v3@870.6,554.18
  Top Layer w10: v3(877.5,715.36) 881.34,715.36 R190.2@891.97,704.73 ; v3(1134.94,540) R189.2@1134.94,562 1134.99,562.05 R176.2@1134.99,592.5 1215.16,592.5 1225.69,581.97 R194.2@1239.41,581.97 R186.1@1270.29,581.97 ; R177.2@1135.83,676.01 R187.2@1135.83,704.35 v3(1135.83,723.6)
  other v3: 871.6,554.18
RADAR_1P0_RF1: C19.2 C23.2 C78.1 C79.1 L3.2 U1.G5 U1.H5 U1.J5 | length 94.3
  Top Layer w12: U1.J5@1100.39,1666.16 U1.G5@1151.57,1666.16
  Top Layer w15: U1.J5@1100.39,1666.16 v2(1100.38,1689.67) ; v2(1146.87,1683.84) 1151.56,1679.15 U1.G5@1151.57,1666.16
RADAR_1P0_RF2: C20.2 C24.2 C76.1 C77.1 L2.2 R1.1 U1.C2 U1.D2 | length 162.3
  Top Layer w20: U1.C2@1254.13,1742.72 1228.54,1742.72 1228.54,1775.5 1268.02,1814.98 v2(1285.98,1814.98)
  Top Layer w25: v2(1285.98,1814.98) 1285.98,1843.73 v2(1286.98,1844.73)
RADAR_1V2: C25.2 C26.2 C27.2 C28.2 C29.2 C30.1 C80.1 C81.1 L7.2 U1.G15 U1.H15 U1.N11 U1.P14 U1.P15 U1.R6 | length 634.2
  Top Layer w10: 960.59,1372.92 972.43,1384.77 U1.P14@972.43,1435.84 ; U1.H15@1125.98,1410.25 1125.97,1357.39 1135.59,1347.77 v2(1136.52,1346.84) 1151.56,1361.88 U1.G15@1151.57,1410.25
  Top Layer w12: C28.2@870.28,1669.77 874.13,1669.77 897.27,1646.63 911.08,1646.63 917.08,1640.63 918.08,1640.63 ; 918.35,1640.36 U1.R6@947.05,1640.36
  Top Layer w15: U1.N11@998.03,1512.61 1003.1,1512.62 v2(1015.27,1524.79)
  Top Layer w20: C27.2@842.09,1364.77 862.55,1344.3 873.86,1344.3 895.28,1322.88 C25.2@895.28,1314.77 932.39,1314.77 960.59,1342.97 960.59,1372.92 ; v2(858.92,1694.27) 858.92,1681.12 C28.2@870.28,1669.77 ; C26.2@1134.5,1320.46 1134.5,1346.68 v2@1135.59,1347.77
  Bottom Layer w20: C29.2@983.87,1495.54 999.57,1495.54 1015.27,1511.24 v2(1015.27,1524.79) ; C30.1@1105,1344.45 v2@1129.04,1344.45
  other v2: 872.95,1385.12 848.87,1401.61
  other v5: 743.79,1957.02 744.02,1992.11
RADAR_1V4_APLL: C22.2 U1.A10 | length 109.3
  Top Layer w12: U1.A10@1305.31,1538 1322.36,1538
  Top Layer w20: 1322.36,1538 1367.36,1538 1380.59,1524.77 C22.2@1409.1,1524.77
RADAR_1V4_SYNTH: C18.2 U1.B13 | length 201.1
  Top Layer w4.5: 1290.62,1472.53 1292.6,1474.52 1317.84,1474.52 1322.59,1469.77
  Top Layer w6: U1.B13@1279.52,1461.43 1290.62,1472.53 ; 1322.59,1469.77 1330.7,1461.65
  Top Layer w15: 1330.7,1461.65 1353.7,1438.66 1366.11,1438.66 1375.89,1428.88 1375.89,1416.47 1397.03,1395.33 C18.2@1397.03,1393.48 ; C18.2@1397.03,1393.48 1397.03,1381.18 C18.2@1405.28,1381.18 1405.28,1385.22 C18.2@1397.03,1393.48
RADAR_1V8: C5.2 C9.2 C10.2 C11.2 C12.2 C13.2 C14.2 C15.2 C82.1 C83.1 L1.2 U1.B11 U1.B12 U1.D15 U1.F5 U1.K5 U1.R9 | length 787.6
  Top Layer w10: v2(900.17,1573.84) 910.21,1563.8 U1.R9@946.84,1563.8 ; U1.D15@1228.54,1410.04 1228.54,1379.17 v2(1232.87,1374.84)
  Top Layer w12: U1.B12@1279.52,1487.02 1338.33,1487.03 1369.18,1456.18 C5.2@1399.5,1456.18 ; v2@1399.5,1430.86 v2(1400.59,1429.77)
  Top Layer w14: U1.B11@1279.52,1512.61 1283.49,1508.64 1351.72,1508.64 1377.59,1482.77 1457.9,1482.77 C14.2@1485.91,1454.77 1500,1468.86 v5(1500,1483.77)
  Top Layer w15: v2(1057,1686.61) 1074.79,1668.82 U1.K5@1074.8,1666.16 ; U1.F5@1177.16,1666.16 1177.15,1670.12 1183.87,1676.84 1183.87,1678.83 1186.34,1681.3 v2(1186.34,1682.84)
  Top Layer w18: v2@1399.5,1430.86 C5.2@1399.5,1456.18
  Bottom Layer w20: v2(900.17,1573.84) 901.1,1574.77 C10.2@940.91,1574.77 ; C11.2@1007.18,1741.49 1007.18,1719.59 1018.43,1708.34 ; C12.2@1161.91,1733.77 1161.67,1733.54 1161.67,1724.09 1186.34,1699.42 v2(1186.34,1682.84) ; C9.2@1200,1389.46 1218.26,1389.45 v2(1232.87,1374.84)
  Bottom Layer w25: 1018.43,1708.34 1035.27,1708.34 v2(1057,1686.61)
  other v3: 1040.43,915.51 1060.35,915.51 1041.12,934.97 1060.01,934.74
  other v5: 1571.06,1418.09 1570.62,1446.1
RADAR_3V3: C16.2 C17.2 C21.2 R150.2 R153.2 R154.2 R156.2 R169.2 R184.2 R200.2 U1.F15 U1.R10 U10.9 | length 1858.8
  Top Layer w8: C16.2@1163.59,1244.46 1163.59,1273.77 1191.29,1301.47 1191.29,1338.34 1177.15,1352.48
  Top Layer w10: v2(885.58,1535.83) 887.75,1538 U1.R10@947.05,1538 ; 1177.15,1352.48 U1.F15@1177.16,1410.25
  Top Layer w12: v5(1874.73,1542.71) 1876.38,1541.06 R169.2@1876.38,1499.77 R150.2@1876.38,1427.68
  Top Layer w15: v2@1136.27,1244.45 C16.2@1163.59,1244.46
  Top Layer w20: C17.2@832.09,1584.77 832.09,1541.58 C21.2@826.28,1535.77 885.52,1535.77 v2(885.58,1535.83)
  L4_SIGNAL 2 w20: v2(855.18,1531.68) 860,1536.51 v2(860,1554.77) 860,1595.01 900.73,1635.74 924.04,1635.74 1037.67,1749.37 1764.79,1749.37 1874.73,1639.43 v5(1874.73,1542.71)
  Bottom Layer w12: R153.2@1859.69,1609.77 R154.2@1859.69,1574.77 1874.73,1559.72 v5(1874.73,1542.71)
  other v2: 1121.21,1230.53 1136.12,1247.85 1107.59,1249.16
RADAR_ANAMUX: R76.1 TP6.1 | length 105.5
  Top Layer w6: R76.1@1490,1249.08 R76.1@1490,1246.15 1496.58,1239.57 1530.98,1239.57 1552,1260.59 TP6.1@1552,1289.77
RADAR_ANATEST2: R73.1 TP3.1 | length 145.2
  Top Layer w8: TP3.1@643.74,1933.67 672.64,1904.77 R73.1@776.97,1904.77
RADAR_ANATEST3: R74.1 TP4.1 | length 60.5
  Top Layer w8: TP4.1@716.44,1814.77 R74.1@776.97,1814.77
RADAR_ANATEST4: R75.1 TP5.1 | length 158.8
  Top Layer w8: TP5.1@629.51,1875.39 650.98,1853.92 771.12,1853.92 R75.1@776.97,1859.77
RADAR_BSS_LOGGER: R60.2 U1.H14 | length 697.3
  Top Layer w4: 1100.16,1299.34 1113.18,1312.36 1113.18,1423.06 U1.H14@1125.98,1435.84
  Top Layer w6: 1100.11,1299.39 1086.39,1285.67 1086.39,1231.85 v2(1118.38,1199.86)
  L5_SIGNAL 3 w6: v2(1118.38,1199.86) 1144.58,1199.86 1161.71,1216.99 1161.71,1251.32 1193.36,1282.97 1216.71,1282.97 1233.47,1266.21 1233.47,1237.97 1281.67,1189.77 v2(1384.83,1189.77)
  Bottom Layer w6: v2(1384.83,1189.77) 1395.9,1200.84 R60.2@1435.75,1200.84
RADAR_CS1: R156.1 U1.E15 U13.10 | length 1278.9
  Top Layer w4: v2(1201.59,1262.77) 1210.29,1271.47 1210.29,1357.43 1202.95,1364.77 U1.E15@1202.95,1410.04
  Top Layer w6: U13.10@694.28,589.07 v2(727.16,589.07)
  L6_SIGNAL 4 w6: v2(727.16,589.07) 766.94,628.86 766.94,711.53 855.93,800.52 919.31,800.52 970,851.21 1150.54,851.21 1181.49,882.15 1181.49,944.15 1153.16,972.48 1153.16,1007.12 1233.17,1087.13 1233.17,1231.19 v2(1201.59,1262.77)
  Bottom Layer w6: v2(1201.59,1262.77) 1227.68,1262.77 R156.1@1230,1265.09
RADAR_DMM_CLK: J6.15 R15.1 U1.N15 | length 3813.7
  Top Layer w4: 976.59,1304.77 976.59,1319.37 998.02,1340.8 U1.N15@998.03,1410.25
  Top Layer w6: 976.59,1304.77 976.59,1144.67 v2(988.18,1133.08) ; R15.1@1876.87,914.52 1857.17,894.83 1857.17,765.81 v2(1879.87,743.11)
  L5_SIGNAL 3 w6: v2(988.18,1133.08) 1046.11,1133.08 1153.29,1025.9 1153.29,980.74 1196.57,937.46 1240.68,937.46 1268.36,909.78 1292.72,909.78 1328.09,874.41 1399.18,874.41 1420.37,895.61 1420.37,923.3 1463.4,966.32 1463.4,1076.91 1598.11,1211.62 1598.11,1288.51 v2(1744.12,1434.52)
  L4_SIGNAL 2 w6: v2(1744.12,1434.52) 1744.12,1427.74 1835.12,1336.74 1835.12,844.64 1879.87,799.89 v2(1879.87,743.11)
  Bottom Layer w6: J6.15@1072.1,343.28 1072.1,386.49 1062.88,395.71 1062.88,456.78 1127.11,521.01 1142.47,521.01 1156.56,535.11 1156.56,581.55 1194.07,619.06 1194.07,635.55 1200.1,641.59 1200.1,674.77 1219.39,694.06 1349.57,694.06 1377.58,722.07 1565.68,722.07 1598.12,689.64 1598.12,661.33 1636.88,622.57 1755.27,622.57 1788.06,589.78 1831.07,589.78 1919.75,678.47 1919.75,700.66 1909.39,711.02 1894.13,711.02 1879.87,725.27 v2(1879.87,743.11)
RADAR_DMM_SYNC: J6.17 R17.1 U1.N14 | length 3932
  Top Layer w4: 960.59,1302.15 960.59,1317.51 985.47,1342.4 985.47,1423.3 U1.N14@998.03,1435.84
  Top Layer w6: 960.59,1302.15 960.59,1119.92 970.2,1110.31 v2(970.79,1110.31) ; R17.1@1876.87,876.15 1876.87,822.66 v2(1906.12,793.41)
  L5_SIGNAL 3 w6: v2(970.79,1110.31) 957.85,1123.25 957.85,1142.11 969.81,1154.07 1045.52,1154.07 1165.29,1034.3 1165.29,985.71 1201.54,949.46 1245.65,949.46 1273.33,921.78 1297.69,921.78 1331.77,887.7 1395.5,887.7 1408.37,900.58 1408.37,928.27 1441.28,961.17 1441.28,1112.89 1572.69,1244.3 1572.69,1300.65 1726.76,1454.72 1756.27,1454.72 v2(1778.25,1432.73)
  L4_SIGNAL 2 w6: v2(1778.25,1432.73) 1847.12,1363.87 1847.12,852.41 v2(1906.12,793.41)
  Bottom Layer w6: J6.17@1091.79,343.28 1091.79,386.67 1078.93,399.53 1078.93,455.86 1130.09,507.02 1145.46,507.02 1170.47,532.03 1170.47,578.2 1206.07,613.8 1206.07,630.58 1212.54,637.05 1212.54,655.3 1212.53,670.22 1223.08,680.77 1237.99,680.77 1353.24,680.76 1382.55,710.07 1560.72,710.07 1586.12,684.67 1586.12,656.31 1631.86,610.57 1740.3,610.57 1774.98,575.89 1774.98,565.2 1793.72,546.46 1817.48,546.46 1830.8,559.78 1830.8,572.54 1833.11,574.85 1932.2,673.93 1932.2,724.4 1934.49,726.69 1934.49,765.04 v2(1906.12,793.41)
RADAR_DP0: J6.19 R18.1 U1.R4 | length 3164.5
  Top Layer w4: 875.43,1744.77 885.59,1744.77 938.61,1691.75 U1.R4@946.84,1691.75
  Top Layer w6: v2(667.85,1795.67) 681.1,1782.42 750.76,1782.42 789.41,1743.77 874.43,1743.77 ; v2(1513.54,1052.59) 1598.92,1052.59 R18.1@1601.77,1055.44
  L3_SIGNAL 1 w6: v2(667.85,1795.67) 603.77,1795.67 485.52,1677.42 485.52,1588.11 525.02,1548.61 540.01,1548.61 564.79,1523.82 564.79,1480.48 571.52,1473.76 583.99,1473.76 601.45,1456.3 632.31,1456.3 650.33,1438.28 840.5,1438.28 874.95,1403.82 888.53,1403.82 968.63,1323.73 968.63,1213.13 1104.66,1077.1 1487.53,1077.1 1512.04,1052.59 v2(1513.54,1052.59)
  L6_SIGNAL 4 w6: v3(1230.53,662.77) 1230.53,763.74 1265.64,798.85 1265.64,939.65 1243.75,961.54 1243.75,973.58 1217.79,999.53 1217.79,1017.05 1227.9,1027.16 1274.84,1027.16 1300.27,1052.59 v2(1513.54,1052.59)
  Bottom Layer w6: J6.19@1111.47,343.28 1111.47,386.49 1092.38,405.58 1092.38,451.93 1135.05,494.6 1150.44,494.6 1183.08,527.24 1183.08,573.83 1218.07,608.83 1218.07,625.61 1230.09,637.63 1230.09,662.77 v3(1230.53,662.77)
RADAR_DP1: J6.21 R19.1 U1.P5 | length 3345
  Top Layer w4: 880.59,1729.77 885.59,1729.77 936.52,1678.84 959.75,1678.84 U1.P5@972.43,1666.16
  Top Layer w6: v2(702.49,1760.45) 750.53,1760.45 781.21,1729.77 880.59,1729.77
  L3_SIGNAL 1 w6: v2(702.49,1760.45) 703.69,1761.65 703.69,1788.4 676.22,1815.87 509.58,1815.87 448.68,1754.97 448.68,1680.15 472.15,1656.67 472.15,1559.59 449.27,1536.7 449.27,1495.29 482.8,1461.76 579.02,1461.76 591.73,1449.05 591.73,1427.25 581.34,1416.86 581.34,1391 593.17,1379.17 606.98,1379.17 650.41,1335.74 711,1335.74 719.39,1344.13 781.41,1344.13 883.31,1242.23 883.31,1193.44 891.8,1184.94 891.8,1150.95 905.09,1137.67 950.94,1137.67 968.37,1155.09 1003.35,1155.09 1094.14,1064.31 1331.46,1064.31 v2(1395,1000.77)
  L6_SIGNAL 4 w6: v2(1120.9,264.37) 1144.67,240.6 1258.7,240.6 1288.89,270.79 1288.89,289.19 1332.94,333.24 1332.94,398.91 1414.33,480.29 1414.33,499.34 1407.21,506.45 1407.21,584.44 1353.66,638 1353.66,776.21 1408.2,830.75 1408.2,922.98 1385.24,945.94 1385.24,991.01 v2(1395,1000.77)
  Bottom Layer w6: v2(1120.9,264.37) 1131.16,274.63 J6.21@1131.16,343.28 ; v2(1395,1000.77) 1420.32,1026.09 R19.1@1435.75,1026.09
RADAR_DP2: J6.23 R20.1 U1.R5 | length 3417.4
  Top Layer w4: 875.59,1714.77 884.86,1714.77 933.68,1665.95 U1.R5@947.05,1665.95
  Top Layer w6: v2(692,1723.83) 717.26,1698.57 804.39,1698.57 820.59,1714.77 875.59,1714.77
  L3_SIGNAL 1 w6: v2(692,1723.83) 694.44,1723.83 724.39,1753.78 724.39,1784.67 678.14,1830.91 507.65,1830.91 430.89,1754.15 430.89,1567.31 437.11,1561.09 437.11,1489.83 477.18,1449.76 533.16,1449.76 555.82,1427.1 555.82,1373.2 616.02,1312.99 717.92,1312.99 731.54,1299.36 790.15,1299.36 849.56,1239.96 849.56,1137.09 904.7,1081.95 974.65,1081.95 998.96,1106.25 1029.76,1106.25 1083.7,1052.31 1302.46,1052.31 v2(1350,1004.77)
  L6_SIGNAL 4 w6: v3(1309.72,280.93) 1344.94,316.15 1344.94,393.94 1426.33,475.32 1426.33,517.18 1421.47,522.04 1421.47,587.16 1368.11,640.52 1368.11,767.12 1428.97,827.98 1428.97,1007.29 1411.83,1024.43 1369.66,1024.43 v2(1350,1004.77)
  Bottom Layer w6: J6.23@1150.84,343.28 1150.33,342.76 1150.33,269.42 1162.16,257.59 1286.38,257.59 v3(1309.72,280.93) ; v2(1350,1004.77) 1370.29,1025.06 R20.1@1370.29,1042.27
RADAR_DP3: J6.25 R21.1 U1.P6 | length 3563.7
  Top Layer w4: v2(768.74,1674.77) 791.74,1651.77 875.16,1651.77 899.09,1627.84 959.7,1627.84 U1.P6@972.43,1640.57
  Top Layer w6: v2(1525.62,1082.63) 1588.88,1082.63 R21.1@1601.77,1095.52
  L3_SIGNAL 1 w6: v2(768.74,1674.77) 740.34,1703.17 682.03,1703.17 666.24,1718.96 544.03,1718.96 497.52,1672.45 497.52,1593.08 529.64,1560.96 544.62,1560.96 576.79,1528.79 576.79,1497.93 606.42,1468.3 637.28,1468.3 655.3,1450.28 842.64,1450.28 879.1,1413.82 895.5,1413.82 984.38,1324.95 984.38,1217.88 1108.6,1093.67 1490.76,1093.67 1501.8,1082.63 v2(1525.62,1082.63)
  L4_SIGNAL 2 w6: v2(1170.53,277.79) 1203.74,311 1232.62,311 1293.13,371.51 1312.53,390.92 1343.45,390.92 1428.5,475.96 1428.5,518.59 1421.47,525.61 1421.47,555.49 1433.3,567.33 1439.54,567.33 1478.56,606.34 1478.56,766.21 1339.49,905.29 1322.74,905.29 1259.73,968.3 1259.73,987.12 1281.32,1008.7 1281.32,1123.61 1374.34,1216.63 1415.78,1216.63 1525.62,1106.79 v2(1525.62,1082.63)
  Bottom Layer w6: v2(1170.53,277.79) J6.25@1170.53,343.28
RADAR_DP4: J6.27 R23.1 U1.R7 | length 2981.5
  Top Layer w4: v2(735.59,1669.77) 761.59,1643.77 871.84,1643.77 895.78,1619.84 941.98,1619.84 U1.R7@946.84,1614.98
  L3_SIGNAL 1 w6: v2(735.59,1669.77) 715.35,1690.01 691.22,1690.01 655.76,1654.55 655.76,1603.84 619.74,1567.83 619.74,1506.81 657.74,1468.82 795.34,1468.82 801.88,1462.28 852.12,1462.28 888.58,1425.82 936.63,1425.82 999.94,1362.51 999.94,1221.23 1113.88,1107.29 1532.34,1107.29 1545.82,1093.82 1545.82,1074.27 1545.81,1040.1 1505.19,999.48 1486.26,999.48 1422.25,935.47 1384.46,935.47 1364.28,915.29 1322.75,915.29 1303.33,934.72 1303.33,973.22 v2(1313.87,983.77)
  L6_SIGNAL 4 w6: v2(1188.67,416.59) 1188.67,469.68 1174.15,484.2 1174.15,522.17 1183.02,531.04 1183.02,581.9 1227.75,626.63 1242.07,626.63 1265.02,649.58 1265.02,689.86 1257.67,697.21 1257.67,754.93 1289.64,786.89 1289.64,926.03 1313.71,950.1 1313.71,983.61 v2(1313.87,983.77)
  Bottom Layer w6: v2(1188.67,416.59) 1188.67,344.82 J6.27@1190.21,343.28 ; v2(1313.87,983.77) 1313.87,1015.9 1360.24,1062.27 R23.1@1430.75,1062.27 R23.1@1435.75,1062.27
RADAR_DP5: J6.29 R26.1 U1.P7 | length 2665.9
  Top Layer w4: v2(700.59,1669.77) 734.59,1635.77 868.53,1635.77 893.46,1610.84 933.27,1610.84 941.67,1602.44 959.89,1602.44 U1.P7@972.43,1614.98
  L3_SIGNAL 1 w6: v2(700.59,1669.77) 711.62,1658.74 711.62,1588.08 700.69,1577.16 690.57,1577.16 656.57,1543.16 656.57,1520.89 672.65,1504.82 810.27,1504.82 815.49,1499.59 916.21,1499.59 923.24,1492.56 ; 923.24,1492.54 1049.94,1365.84 1049.94,1233.01 1139.66,1143.29 1357.73,1143.29 v2(1368.44,1154)
  L4_SIGNAL 2 w6: v2(1219.22,280.64) 1305.13,366.54 ; 1305.13,366.55 1340.22,366.55 1474.68,501.01 1474.68,585.49 1490.56,601.38 1490.56,837.67 1384.27,943.96 1384.27,971.13 1374.1,981.3 1374.1,1090.72 1368.44,1096.38 v2(1368.44,1154)
  Bottom Layer w6: J6.29@1209.9,343.28 1209.9,289.96 v2(1219.22,280.64) ; v2(1368.44,1154) 1368.44,1130.26 1401.79,1096.91 R26.1@1430.75,1096.91 R26.1@1435.75,1096.91
RADAR_DP6: J6.31 R27.1 U1.R8 | length 2654.3
  Top Layer w4: v2(690.59,1639.77) 702.59,1627.77 865.22,1627.77 892.36,1600.63 927.48,1600.63 938.72,1589.39 U1.R8@946.84,1589.39
  L3_SIGNAL 1 w6: v2(690.59,1639.77) 667.76,1616.93 667.76,1592.9 632.57,1557.71 632.57,1510.95 662.71,1480.82 800.31,1480.82 806.85,1474.28 905.44,1474.28 1014.5,1365.22 1014.5,1228.31 1123.52,1119.29 1394.52,1119.29 v2(1405,1129.77)
  L6_SIGNAL 4 w6: v2(1218.61,417.96) 1189.19,388.55 1111.95,388.55 1094.03,406.47 1094.03,464.54 1171.02,541.54 1171.02,631.33 1161.12,641.23 1161.12,659.41 1194.34,692.64 1194.34,951.97 1165.16,981.15 1165.16,1002.15 1231.21,1068.2 1343.43,1068.2 v2(1405,1129.77)
  Bottom Layer w6: v2(1218.61,417.96) 1229.58,406.99 J6.31@1229.58,343.28 ; v2(1405,1129.77) 1433.97,1129.77 R27.1@1435.75,1131.56
RADAR_DP7: J6.33 R28.1 U1.P8 | length 2919.8
  Top Layer w4: v2(690.59,1604.77) 705.59,1619.77 861.9,1619.77 889.04,1592.63 917.42,1592.63 933.37,1576.68 960.14,1576.68 U1.P8@972.64,1589.18
  L3_SIGNAL 1 w6: v2(690.59,1604.77) 679.27,1593.45 679.27,1585.89 644.57,1551.19 644.57,1515.92 667.68,1492.82 805.3,1492.82 810.51,1487.61 ; 810.51,1487.59 911.24,1487.59 1034.19,1364.64 1034.19,1229.11 1132.01,1131.29 1374.3,1131.29 1390.36,1147.36 1390.36,1154.22 v2(1406.71,1170.57) 1491.4,1170.57 1558.23,1103.74 1558.23,967.41 1540.32,949.51 1540.32,560.94 1523.43,544.04 1523.43,513.26 1577.76,458.94 1577.76,328.89 1531.47,282.6 1531.47,259.47 1502.61,230.62 1379,230.62 1352.5,257.12 1287.17,257.12 v2(1266.48,277.81)
  Bottom Layer w6: J6.33@1249.27,343.28 1249.27,295.03 v2(1266.48,277.81) ; v2(1406.71,1170.57) 1431.38,1170.57 R28.1@1435.75,1166.2
RADAR_DP8: R124.1 R148.1 | length 1285.5
  L4_SIGNAL 2 w6: v2(744.64,1323.16) 710.09,1323.16 661.21,1274.28 661.21,1093.27 694.92,1059.57 694.92,879.76 736.54,838.14 773.94,838.14 868.08,744 879.35,744 928.78,694.57 1039.52,694.57 1083.75,650.35 1083.75,625.74 v2(1196.95,512.54)
  Bottom Layer w6: R124.1@671.74,1329.77 674.85,1329.77 681.46,1323.16 v2(744.64,1323.16) ; R148.1@1196.95,483.45 v2(1196.95,512.54)
RADAR_DP9: R125.1 R149.1 | length 1228.1
  L5_SIGNAL 3 w6: v2(780.44,1189.35) 780.44,1170.42 871.95,1078.91 871.95,1037.77 837.07,1002.89 837.07,706.21 870.04,673.24 1069.47,673.24 1218.86,523.84 1218.86,516.02 v2(1228.2,506.69)
  Bottom Layer w6: R125.1@671.74,1294.77 695.99,1294.77 720.97,1269.79 720.97,1210.2 741.82,1189.35 v2(780.44,1189.35) ; v2(1228.2,506.69) 1228.2,488.32 R149.1@1234.31,482.2
RADAR_DP10: R126.1 R163.1 | length 1440
  L3_SIGNAL 1 w6: v2(699.88,1262.31) 619.04,1181.47 619.04,1031.78 679.65,971.18 679.65,913.63 760.82,832.46 797.34,832.46 804.96,824.84 950.77,824.84 977.15,851.21 1032.87,851.21 1065.23,818.85 1155.14,818.85 1239.93,734.06 1239.93,717.61 1329.48,628.05 1329.48,569.87 1306.87,547.26 1306.87,529.59 1315.67,520.79 v2(1315.67,506.35)
  Bottom Layer w6: R126.1@656.74,1259.77 659.27,1262.31 v2(699.88,1262.31) ; R163.1@1271.67,482.2 1271.67,482.61 1295.41,506.35 v2(1315.67,506.35)
RADAR_DP11: R127.1 R164.1 | length 1390.6
  L3_SIGNAL 1 w6: v2(700.77,1224.08) 686.3,1224.08 631.92,1169.7 631.92,1039.89 691.77,980.04 691.77,921.47 768.79,844.46 802.31,844.46 809.93,836.84 944.98,836.84 971.35,863.21 1037.85,863.21 1070.2,830.85 1161.65,830.85 1251.93,740.57 1251.93,722.58 1341.48,633.03 1341.48,553.3 v2(1327.07,538.89)
  Bottom Layer w6: R127.1@656.74,1224.77 657.43,1224.08 v2(700.77,1224.08) ; R164.1@1311.95,476.21 1318.5,482.76 1324.58,482.76 1336.41,494.6 1336.41,514.17 1327.07,523.51 v2(1327.07,538.89)
RADAR_DP12: R128.1 R166.1 | length 1313
  L3_SIGNAL 1 w6: v2(702.64,1192.32) 687.92,1192.32 647.04,1151.44 647.04,1047.9 713.7,981.24 765.35,981.24 806.14,940.45 806.14,910.34 867.64,848.84 914.85,848.84 941.22,875.21 1042.82,875.21 1075.17,842.85 1166.62,842.85 1263.93,745.54 1263.93,727.55 1355.47,636 v2(1355.47,529.24)
  Bottom Layer w6: R128.1@656.74,1189.77 659.28,1192.32 v2(702.64,1192.32) ; R166.1@1352.68,476.21 1355.47,479 v2(1355.47,529.24)
RADAR_DP13: R129.1 R167.1 | length 1774.4
  L4_SIGNAL 2 w6: v2(701,1162.39) 673.21,1190.18 673.21,1269.31 706.86,1302.96 986.35,1302.96 1154.49,1134.82 1154.49,995.55 1193.3,956.74 1236.32,956.74 1312.09,880.97 1329.87,880.97 1452.29,758.55 1452.29,617.94 1436.42,602.07 1354.52,602.07 1295.47,543.01 1295.47,495.14 1307.84,482.76 1342.8,482.76 1351.01,490.97 v2(1394.13,490.97)
  Bottom Layer w6: R129.1@656.74,1159.77 659.35,1162.39 v2(701,1162.39) ; R167.1@1390.77,465.36 1394.13,468.72 v2(1394.13,490.97)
